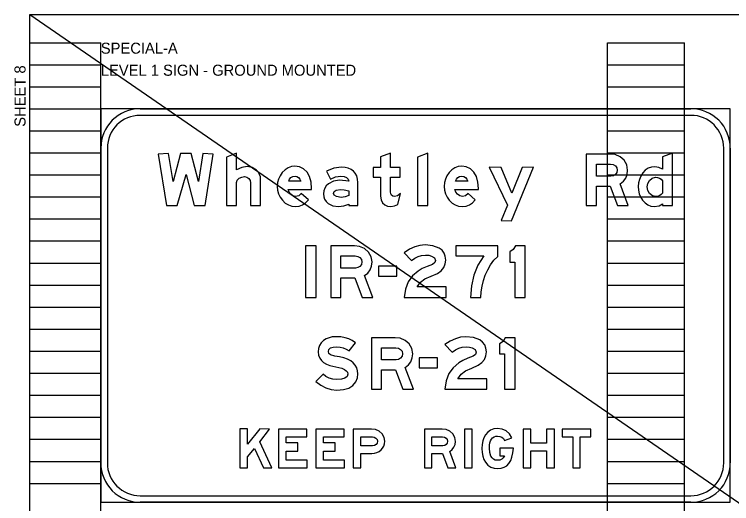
# Model space of a CAD drawing. Extents: x 1820207 to 1820557, y 740216 to 740315.
# Drawn here: x 1820476.25 to 1820485.37, y 740308.38 to 740314.6 of the extents above; entities that cross this region are included whole.
import ezdxf

# ---------------------------------------------------------------- set-up
doc = ezdxf.new("R2010")
doc.units = 0
for name, color, linetype in [('SC_Scratch1', 7, 'Continuous'), ('SC_Scratch2', 7, 'Continuous'), ('SC_Scratch3', 7, 'Continuous'), ('SC_Shading1', 7, 'Continuous'), ('SH_Text', 7, 'Continuous')]:
    doc.layers.add(name, color=color, linetype=linetype)

msp = doc.modelspace()

# ---------------------------------------------------------------- linework, layer by layer
at = {"layer": 'SC_Scratch1'}
for p, q in [((1820476.451, 740294.0812), (1820476.451, 740314.2412)), ((1820476.451, 740314.2412), (1820477.351, 740314.2412)), ((1820477.351, 740294.0812), (1820477.351, 740314.2412)), ((1820483.791, 740294.0812), (1820483.791, 740314.2412)), ((1820483.791, 740314.2412), (1820484.771, 740314.2412)), ((1820484.771, 740294.0812), (1820484.771, 740314.2412)), ((1820476.451, 740313.9612), (1820477.351, 740313.9612)), ((1820483.791, 740313.9612), (1820484.771, 740313.9612)), ((1820476.451, 740313.6812), (1820477.351, 740313.6812)), ((1820483.791, 740313.6812), (1820484.771, 740313.6812)), ((1820476.451, 740313.4012), (1820477.351, 740313.4012)), ((1820483.791, 740313.4012), (1820484.771, 740313.4012)), ((1820476.451, 740313.1212), (1820477.351, 740313.1212)), ((1820483.791, 740313.1212), (1820484.771, 740313.1212)), ((1820476.451, 740312.8412), (1820477.351, 740312.8412)), ((1820483.791, 740312.8412), (1820484.771, 740312.8412)), ((1820476.451, 740312.5612), (1820477.351, 740312.5612)), ((1820483.791, 740312.5612), (1820484.771, 740312.5612)), ((1820476.451, 740312.2812), (1820477.351, 740312.2812)), ((1820483.791, 740312.2812), (1820484.771, 740312.2812)), ((1820476.451, 740312.0012), (1820477.351, 740312.0012)), ((1820483.791, 740312.0012), (1820484.771, 740312.0012)), ((1820476.451, 740311.7212), (1820477.351, 740311.7212)), ((1820483.791, 740311.7212), (1820484.771, 740311.7212)), ((1820476.451, 740311.4412), (1820477.351, 740311.4412)), ((1820483.791, 740311.4412), (1820484.771, 740311.4412)), ((1820476.451, 740311.1612), (1820477.351, 740311.1612)), ((1820483.791, 740311.1612), (1820484.771, 740311.1612)), ((1820476.451, 740310.8812), (1820477.351, 740310.8812)), ((1820483.791, 740310.8812), (1820484.771, 740310.8812)), ((1820476.451, 740310.6012), (1820477.351, 740310.6012)), ((1820483.791, 740310.6012), (1820484.771, 740310.6012)), ((1820476.451, 740310.3212), (1820477.351, 740310.3212)), ((1820483.791, 740310.3212), (1820484.771, 740310.3212)), ((1820476.451, 740310.0412), (1820477.351, 740310.0412)), ((1820483.791, 740310.0412), (1820484.771, 740310.0412)), ((1820476.451, 740309.7612), (1820477.351, 740309.7612)), ((1820483.791, 740309.7612), (1820484.771, 740309.7612)), ((1820476.451, 740309.4812), (1820477.351, 740309.4812)), ((1820483.791, 740309.4812), (1820484.771, 740309.4812)), ((1820476.451, 740309.2012), (1820477.351, 740309.2012)), ((1820483.791, 740309.2012), (1820484.771, 740309.2012)), ((1820476.451, 740308.9212), (1820477.351, 740308.9212)), ((1820483.791, 740308.9212), (1820484.771, 740308.9212)), ((1820476.451, 740308.6412), (1820477.351, 740308.6412)), ((1820483.791, 740308.6412), (1820484.771, 740308.6412))]:
    msp.add_line(p, q, dxfattribs=at)
at = {"layer": 'SC_Scratch2'}
msp.add_lwpolyline([(1820476.451, 740314.6012), (1820506.951, 740314.6012), (1820506.951, 740293.6012), (1820476.451, 740293.6012)], close=True, dxfattribs=at)
at = {"layer": 'SC_Scratch3'}
for points in [[(1820477.351, 740308.4012), (1820485.351, 740308.4012), (1820485.351, 740313.4012), (1820477.351, 740313.4012), (1820477.351, 740308.4012), (1820477.351, 740308.4012), (1820477.351, 740308.4012)], [(1820477.851, 740313.4012), (1820484.851, 740313.4012)], [(1820484.851, 740313.3178), (1820477.851, 740313.3178)], [(1820484.851, 740313.3178), (1820484.851, 740313.3178), (1820484.851, 740313.3178)], [(1820477.351, 740308.9012), (1820477.351, 740312.9012)], [(1820477.4343, 740312.9012), (1820477.4343, 740308.9012)], [(1820477.4343, 740312.9012), (1820477.4343, 740312.9012), (1820477.4343, 740312.9012)], [(1820485.2676, 740308.9012), (1820485.2676, 740312.9012)], [(1820485.351, 740312.9012), (1820485.351, 740308.9012)], [(1820485.2676, 740308.9012), (1820485.2676, 740308.9012), (1820485.2676, 740308.9012)], [(1820477.851, 740308.4845), (1820484.851, 740308.4845)], [(1820477.851, 740308.4845), (1820477.851, 740308.4845), (1820477.851, 740308.4845)], [(1820484.851, 740308.4012), (1820477.851, 740308.4012)]]:
    msp.add_lwpolyline(points, dxfattribs=at)
for points in [[(1820478.1845, 740312.172), (1820478.3229, 740312.172), (1820478.4363, 740312.567), (1820478.5378, 740312.172), (1820478.6763, 740312.172), (1820478.7799, 740312.8258), (1820478.6487, 740312.8312), (1820478.5933, 740312.4778), (1820478.501, 740312.8312), (1820478.3624, 740312.8312), (1820478.2702, 740312.4778), (1820478.2121, 740312.8312), (1820478.081, 740312.8258)], [(1820478.9476, 740312.172), (1820479.0758, 740312.172), (1820479.0758, 740312.4652), (1820479.0846, 740312.4945), (1820479.1113, 740312.5193), (1820479.1433, 740312.5341), (1820479.1768, 740312.5392), (1820479.2074, 740312.5333), (1820479.2326, 740312.5161), (1820479.2495, 740312.4907), (1820479.2552, 740312.4607), (1820479.2552, 740312.172), (1820479.3827, 740312.172), (1820479.3827, 740312.5049), (1820479.3793, 740312.5377), (1820479.3697, 740312.5682), (1820479.3532, 740312.5958), (1820479.3306, 740312.6211), (1820479.2749, 740312.6552), (1820479.2096, 740312.6666), (1820479.1449, 740312.6565), (1820479.0758, 740312.6269), (1820479.0758, 740312.8387), (1820478.9476, 740312.7881)], [(1820480.8143, 740312.531), (1820480.9052, 740312.531), (1820480.9046, 740312.2911), (1820480.9132, 740312.2441), (1820480.932, 740312.2059), (1820480.9591, 740312.179), (1820480.9943, 740312.1635), (1820481.0378, 740312.1592), (1820481.0833, 740312.1666), (1820481.1242, 740312.1854), (1820481.1584, 740312.325), (1820481.1238, 740312.2968), (1820481.0833, 740312.2873), (1820481.0614, 740312.291), (1820481.0461, 740312.302), (1820481.0368, 740312.3202), (1820481.0338, 740312.3458), (1820481.0338, 740312.531), (1820481.1572, 740312.531), (1820481.1572, 740312.6534), (1820481.0338, 740312.6534), (1820481.0338, 740312.8387), (1820480.9052, 740312.7888), (1820480.9052, 740312.6534), (1820480.8143, 740312.6534)], [(1820481.3743, 740312.172), (1820481.506, 740312.172), (1820481.506, 740312.8387), (1820481.3743, 740312.7881)], [(1820483.9502, 740312.4478), (1820483.9919, 740312.4811), (1820484.0217, 740312.5211), (1820484.0398, 740312.5678), (1820484.0458, 740312.6211), (1820484.0345, 740312.6874), (1820484.0013, 740312.7463), (1820483.9506, 740312.7921), (1820483.8875, 740312.8192), (1820483.8202, 740312.8258), (1820483.521, 740312.8258), (1820483.521, 740312.172), (1820483.6491, 740312.172), (1820483.6491, 740312.4179), (1820483.8262, 740312.4179), (1820483.9183, 740312.172), (1820484.055, 740312.172)], [(1820484.4886, 740312.172), (1820484.616, 740312.172), (1820484.616, 740312.8387), (1820484.4886, 740312.789), (1820484.4886, 740312.6321), (1820484.4429, 740312.6567), (1820484.3933, 740312.6652), (1820484.3486, 740312.6601), (1820484.3082, 740312.6452), (1820484.2713, 740312.6201), (1820484.2386, 740312.5853), (1820484.2133, 740312.5462), (1820484.1954, 740312.5043), (1820484.1845, 740312.4594), (1820484.181, 740312.4118), (1820484.1843, 740312.3657), (1820484.1945, 740312.3222), (1820484.2118, 740312.2807), (1820484.236, 740312.2419), (1820484.2679, 740312.2055), (1820484.3034, 740312.1798), (1820484.3422, 740312.1642), (1820484.3848, 740312.1592), (1820484.4454, 740312.168), (1820484.4886, 740312.1944)], [(1820479.9899, 740312.2461), (1820479.8995, 740312.3257), (1820479.8673, 740312.2968), (1820479.8264, 740312.2873), (1820479.7933, 740312.2942), (1820479.7645, 740312.3152), (1820479.7433, 740312.3435), (1820479.7315, 740312.3771), (1820480.0294, 740312.3771), (1820480.0294, 740312.3882), (1820480.0236, 740312.4707), (1820480.0049, 740312.5395), (1820479.9729, 740312.5949), (1820479.9278, 740312.6369), (1820479.8749, 740312.6631), (1820479.819, 740312.672), (1820479.7729, 740312.6668), (1820479.7307, 740312.6515), (1820479.6922, 740312.6261), (1820479.6575, 740312.5909), (1820479.6297, 740312.5508), (1820479.6101, 740312.5083), (1820479.598, 740312.463), (1820479.5943, 740312.4152), (1820479.5983, 740312.3659), (1820479.6105, 740312.3202), (1820479.6309, 740312.2776), (1820479.6596, 740312.2383), (1820479.6952, 740312.2034), (1820479.7351, 740312.1788), (1820479.7788, 740312.164), (1820479.8264, 740312.1592), (1820479.8723, 740312.1646), (1820479.9149, 740312.1808), (1820479.954, 740312.2078)], [(1820480.5014, 740312.172), (1820480.6166, 740312.172), (1820480.6166, 740312.463), (1820480.613, 740312.5081), (1820480.6028, 740312.5477), (1820480.5853, 740312.5816), (1820480.5613, 740312.6101), (1820480.5317, 740312.6313), (1820480.4966, 740312.6467), (1820480.4558, 740312.656), (1820480.4097, 740312.6591), (1820480.3138, 740312.6467), (1820480.2203, 740312.6097), (1820480.2697, 740312.5089), (1820480.3352, 740312.535), (1820480.4003, 740312.5438), (1820480.4432, 740312.5398), (1820480.4744, 740312.5281), (1820480.4936, 740312.5085), (1820480.5014, 740312.4813), (1820480.3864, 740312.4925), (1820480.3089, 740312.4815), (1820480.2448, 740312.4484), (1820480.2168, 740312.4223), (1820480.1967, 740312.3923), (1820480.1847, 740312.3583), (1820480.181, 740312.3202), (1820480.1845, 740312.2833), (1820480.1955, 740312.2509), (1820480.2138, 740312.2226), (1820480.2394, 740312.1986), (1820480.2995, 740312.1691), (1820480.3738, 740312.1592), (1820480.4399, 740312.1665), (1820480.5014, 740312.1884)], [(1820482.1099, 740312.2461), (1820482.0195, 740312.3257), (1820481.9873, 740312.2968), (1820481.9464, 740312.2873), (1820481.9133, 740312.2942), (1820481.8845, 740312.3152), (1820481.8633, 740312.3435), (1820481.8515, 740312.3771), (1820482.1494, 740312.3771), (1820482.1494, 740312.3882), (1820482.1436, 740312.4707), (1820482.1249, 740312.5395), (1820482.0929, 740312.5949), (1820482.0478, 740312.6369), (1820481.9949, 740312.6631), (1820481.939, 740312.672), (1820481.8929, 740312.6668), (1820481.8507, 740312.6515), (1820481.8122, 740312.6261), (1820481.7775, 740312.5909), (1820481.7497, 740312.5508), (1820481.7301, 740312.5083), (1820481.718, 740312.463), (1820481.7143, 740312.4152), (1820481.7183, 740312.3659), (1820481.7305, 740312.3202), (1820481.7509, 740312.2776), (1820481.7796, 740312.2383), (1820481.8152, 740312.2034), (1820481.8551, 740312.1788), (1820481.8988, 740312.164), (1820481.9464, 740312.1592), (1820481.9923, 740312.1646), (1820482.0349, 740312.1808), (1820482.074, 740312.2078)], [(1820482.2876, 740312.6591), (1820482.5178, 740312.1752), (1820482.4379, 740311.9797), (1820482.5711, 740311.9775), (1820482.8481, 740312.6591), (1820482.7071, 740312.6534), (1820482.5738, 740312.3288), (1820482.4398, 740312.6534)], [(1820483.9152, 740312.6217), (1820483.9091, 740312.5902), (1820483.8915, 740312.5654), (1820483.865, 740312.5492), (1820483.8335, 740312.5438), (1820483.6491, 740312.5438), (1820483.6491, 740312.6976), (1820483.8306, 740312.6976), (1820483.8631, 740312.6924), (1820483.8905, 740312.677), (1820483.909, 740312.6527)], [(1820479.8949, 740312.4796), (1820479.7387, 740312.4796), (1820479.7507, 740312.5077), (1820479.7681, 740312.5277), (1820479.791, 740312.5398), (1820479.8192, 740312.5438), (1820479.8435, 740312.5398), (1820479.8641, 740312.5277), (1820479.8811, 740312.5077)], [(1820482.0149, 740312.4796), (1820481.8587, 740312.4796), (1820481.8707, 740312.5077), (1820481.8881, 740312.5277), (1820481.911, 740312.5398), (1820481.9392, 740312.5438), (1820481.9635, 740312.5398), (1820481.9841, 740312.5277), (1820482.0011, 740312.5077)], [(1820484.4886, 740312.3302), (1820484.474, 740312.3114), (1820484.4555, 740312.298), (1820484.4327, 740312.2899), (1820484.4063, 740312.2873), (1820484.3606, 740312.2966), (1820484.3248, 740312.3244), (1820484.3034, 740312.3623), (1820484.2963, 740312.4075), (1820484.3027, 740312.4516), (1820484.3226, 740312.4907), (1820484.3562, 740312.5207), (1820484.3995, 740312.531), (1820484.4275, 740312.528), (1820484.452, 740312.5195), (1820484.4722, 740312.5051), (1820484.4886, 740312.4855)], [(1820480.5014, 740312.2988), (1820480.4568, 740312.2806), (1820480.4047, 740312.2745), (1820480.3448, 740312.2858), (1820480.3179, 740312.3034), (1820480.3091, 740312.3268), (1820480.3169, 740312.3505), (1820480.3404, 740312.3671), (1820480.3956, 740312.3771), (1820480.4459, 740312.3723), (1820480.5014, 740312.3579)], [(1820479.9543, 740311.0053), (1820480.086, 740311.0053), (1820480.086, 740311.6591), (1820479.9543, 740311.6591)], [(1820480.7036, 740311.2811), (1820480.7452, 740311.3144), (1820480.775, 740311.3545), (1820480.7931, 740311.4012), (1820480.7991, 740311.4544), (1820480.7879, 740311.5207), (1820480.7546, 740311.5796), (1820480.704, 740311.6255), (1820480.6408, 740311.6526), (1820480.5735, 740311.6591), (1820480.2743, 740311.6591), (1820480.2743, 740311.0053), (1820480.4025, 740311.0053), (1820480.4025, 740311.2513), (1820480.5795, 740311.2513), (1820480.6717, 740311.0053), (1820480.8083, 740311.0053)], [(1820481.2076, 740311.0053), (1820481.7416, 740311.0053), (1820481.7416, 740311.1371), (1820481.3719, 740311.1371), (1820481.4145, 740311.1968), (1820481.4694, 740311.2397), (1820481.5506, 740311.2737), (1820481.6302, 740311.3092), (1820481.676, 740311.344), (1820481.7088, 740311.3841), (1820481.7285, 740311.429), (1820481.7351, 740311.4789), (1820481.7296, 740311.5265), (1820481.7138, 740311.5678), (1820481.6874, 740311.6027), (1820481.6507, 740311.6313), (1820481.5718, 740311.6618), (1820481.4726, 740311.672), (1820481.4073, 740311.6656), (1820481.3414, 740311.6467), (1820481.2747, 740311.6153), (1820481.2076, 740311.5714), (1820481.3006, 740311.4755), (1820481.341, 740311.5049), (1820481.3839, 740311.5259), (1820481.4287, 740311.5385), (1820481.476, 740311.5428), (1820481.5183, 740311.5395), (1820481.5558, 740311.5302), (1820481.5928, 740311.5075), (1820481.6052, 740311.4755), (1820481.595, 740311.4476), (1820481.565, 740311.4234), (1820481.499, 740311.3978), (1820481.437, 740311.3711), (1820481.3831, 740311.3397), (1820481.312, 740311.2781), (1820481.2593, 740311.2022), (1820481.2242, 740311.1111)], [(1820481.861, 740311.5347), (1820482.2183, 740311.5347), (1820482.1446, 740311.4142), (1820482.0921, 740311.2859), (1820482.0607, 740311.1495), (1820482.0502, 740311.0053), (1820482.182, 740311.0053), (1820482.1854, 740311.0762), (1820482.1958, 740311.1469), (1820482.2131, 740311.2173), (1820482.2375, 740311.2872), (1820482.2688, 740311.3567), (1820482.3055, 740311.4196), (1820482.3475, 740311.4759), (1820482.395, 740311.5258), (1820482.395, 740311.6591), (1820481.861, 740311.6591)], [(1820482.6115, 740311.0053), (1820482.7453, 740311.0053), (1820482.7453, 740311.6591), (1820482.6207, 740311.6591), (1820482.593, 740311.6128), (1820482.5476, 740311.5827), (1820482.5476, 740311.4536), (1820482.6115, 740311.4536)], [(1820480.6685, 740311.455), (1820480.6625, 740311.4236), (1820480.6448, 740311.3987), (1820480.6184, 740311.3825), (1820480.5868, 740311.3771), (1820480.4025, 740311.3771), (1820480.4025, 740311.531), (1820480.5839, 740311.531), (1820480.6164, 740311.5258), (1820480.6438, 740311.5103), (1820480.6623, 740311.4861)], [(1820481.1117, 740311.4027), (1820480.881, 740311.4027), (1820480.881, 740311.2745), (1820481.1117, 740311.2745)], [(1820480.0843, 740309.9372), (1820480.1461, 740309.8883), (1820480.2117, 740309.8536), (1820480.2803, 740309.8327), (1820480.3527, 740309.8259), (1820480.4346, 740309.8325), (1820480.5019, 740309.8524), (1820480.5546, 740309.8859), (1820480.5927, 740309.933), (1820480.6119, 740309.9804), (1820480.6183, 740310.0317), (1820480.6145, 740310.073), (1820480.6037, 740310.1102), (1820480.5853, 740310.1434), (1820480.5598, 740310.1726), (1820480.527, 740310.1974), (1820480.4869, 740310.2182), (1820480.4394, 740310.2348), (1820480.3849, 740310.2475), (1820480.327, 740310.2561), (1820480.2715, 740310.2728), (1820480.2507, 740310.2906), (1820480.2439, 740310.317), (1820480.2506, 740310.3432), (1820480.271, 740310.3621), (1820480.305, 740310.3735), (1820480.3527, 740310.3773), (1820480.3935, 740310.3739), (1820480.4332, 740310.3639), (1820480.4711, 740310.3471), (1820480.5076, 740310.3238), (1820480.588, 740310.4262), (1820480.5466, 740310.4555), (1820480.5049, 740310.477), (1820480.456, 740310.4926), (1820480.4, 740310.5021), (1820480.3369, 740310.5053), (1820480.2932, 740310.5021), (1820480.2529, 740310.4926), (1820480.216, 740310.4769), (1820480.1824, 740310.4548), (1820480.1523, 740310.4253), (1820480.1309, 740310.3919), (1820480.1181, 740310.3543), (1820480.1139, 740310.3126), (1820480.1189, 740310.2719), (1820480.1343, 740310.2321), (1820480.1546, 740310.2018), (1820480.1824, 740310.1762), (1820480.2178, 740310.1552), (1820480.261, 740310.1389), (1820480.4146, 740310.1035), (1820480.447, 740310.0902), (1820480.4704, 740310.0732), (1820480.4843, 740310.0524), (1820480.4891, 740310.0276), (1820480.4803, 740309.9981), (1820480.4541, 740309.9773), (1820480.4104, 740309.9647), (1820480.3493, 740309.9607), (1820480.2994, 740309.9648), (1820480.2541, 740309.9781), (1820480.213, 740309.9997), (1820480.1766, 740310.0306)], [(1820481.2202, 740310.1145), (1820481.2619, 740310.1478), (1820481.2917, 740310.1878), (1820481.3098, 740310.2345), (1820481.3158, 740310.2877), (1820481.3045, 740310.3541), (1820481.2713, 740310.413), (1820481.2206, 740310.4588), (1820481.1575, 740310.4859), (1820481.0902, 740310.4925), (1820480.791, 740310.4925), (1820480.791, 740309.8387), (1820480.9191, 740309.8387), (1820480.9191, 740310.0846), (1820481.0962, 740310.0846), (1820481.1883, 740309.8387), (1820481.325, 740309.8387)], [(1820481.7243, 740309.8387), (1820482.2583, 740309.8387), (1820482.2583, 740309.9704), (1820481.8885, 740309.9704), (1820481.9312, 740310.0302), (1820481.9861, 740310.073), (1820482.0672, 740310.1071), (1820482.1469, 740310.1425), (1820482.1926, 740310.1774), (1820482.2254, 740310.2174), (1820482.2451, 740310.2623), (1820482.2517, 740310.3122), (1820482.2463, 740310.3598), (1820482.2305, 740310.4012), (1820482.204, 740310.436), (1820482.1673, 740310.4647), (1820482.0885, 740310.4951), (1820481.9893, 740310.5053), (1820481.924, 740310.4989), (1820481.8581, 740310.48), (1820481.7913, 740310.4486), (1820481.7243, 740310.4048), (1820481.8172, 740310.3088), (1820481.8577, 740310.3383), (1820481.9006, 740310.3593), (1820481.9454, 740310.3719), (1820481.9927, 740310.3761), (1820482.0349, 740310.3729), (1820482.0724, 740310.3635), (1820482.1095, 740310.3409), (1820482.1219, 740310.3088), (1820482.1117, 740310.281), (1820482.0816, 740310.2567), (1820482.0157, 740310.2311), (1820481.9536, 740310.2044), (1820481.8997, 740310.173), (1820481.8286, 740310.1115), (1820481.776, 740310.0355), (1820481.7409, 740309.9444)], [(1820482.4815, 740309.8387), (1820482.6153, 740309.8387), (1820482.6153, 740310.4925), (1820482.4907, 740310.4925), (1820482.463, 740310.4462), (1820482.4176, 740310.416), (1820482.4176, 740310.2869), (1820482.4815, 740310.2869)], [(1820481.1852, 740310.2884), (1820481.1791, 740310.2569), (1820481.1615, 740310.2321), (1820481.135, 740310.2159), (1820481.1035, 740310.2104), (1820480.9191, 740310.2104), (1820480.9191, 740310.3643), (1820481.1006, 740310.3643), (1820481.1331, 740310.3591), (1820481.1605, 740310.3436), (1820481.179, 740310.3194)], [(1820481.6283, 740310.2361), (1820481.3976, 740310.2361), (1820481.3976, 740310.1079), (1820481.6283, 740310.1079)], [(1820479.1185, 740308.8387), (1820479.2153, 740308.8387), (1820479.2153, 740308.9787), (1820479.3028, 740309.0845), (1820479.4171, 740308.8387), (1820479.5264, 740308.8387), (1820479.3701, 740309.1677), (1820479.4952, 740309.329), (1820479.3721, 740309.3331), (1820479.2153, 740309.1377), (1820479.2153, 740309.3331), (1820479.1185, 740309.3331)], [(1820479.9744, 740308.9348), (1820479.7049, 740308.9348), (1820479.7049, 740309.0502), (1820479.8538, 740309.0502), (1820479.8538, 740309.1559), (1820479.7049, 740309.1559), (1820479.7049, 740309.2329), (1820479.9675, 740309.2329), (1820479.9675, 740309.329), (1820479.6085, 740309.329), (1820479.6085, 740308.8387), (1820479.9744, 740308.8387)], [(1820480.4494, 740308.9348), (1820480.1799, 740308.9348), (1820480.1799, 740309.0502), (1820480.3288, 740309.0502), (1820480.3288, 740309.1559), (1820480.1799, 740309.1559), (1820480.1799, 740309.2329), (1820480.4425, 740309.2329), (1820480.4425, 740309.329), (1820480.0835, 740309.329), (1820480.0835, 740308.8387), (1820480.4494, 740308.8387)], [(1820480.5585, 740308.8387), (1820480.6546, 740308.8387), (1820480.6546, 740309.0231), (1820480.7964, 740309.0231), (1820480.8298, 740309.0257), (1820480.8603, 740309.0337), (1820480.8879, 740309.0469), (1820480.9125, 740309.0655), (1820480.9327, 740309.0882), (1820480.9473, 740309.1143), (1820480.956, 740309.1436), (1820480.959, 740309.1764), (1820480.9507, 740309.2255), (1820480.9264, 740309.2695), (1820480.8893, 740309.3039), (1820480.8433, 740309.3242), (1820480.7933, 740309.329), (1820480.5585, 740309.329)], [(1820481.7854, 740309.0455), (1820481.8167, 740309.0705), (1820481.839, 740309.1005), (1820481.8526, 740309.1355), (1820481.8571, 740309.1755), (1820481.8487, 740309.2252), (1820481.8237, 740309.2694), (1820481.7857, 740309.3038), (1820481.7384, 740309.3241), (1820481.6879, 740309.329), (1820481.4635, 740309.329), (1820481.4635, 740308.8387), (1820481.5596, 740308.8387), (1820481.5596, 740309.0231), (1820481.6924, 740309.0231), (1820481.7615, 740308.8387), (1820481.864, 740308.8387)], [(1820481.9735, 740308.8387), (1820482.0723, 740308.8387), (1820482.0723, 740309.329), (1820481.9735, 740309.329)], [(1820482.4242, 740309.0887), (1820482.4242, 740308.9925), (1820482.4831, 740308.9925), (1820482.4666, 740308.9673), (1820482.4458, 740308.9492), (1820482.4209, 740308.9384), (1820482.3919, 740308.9348), (1820482.365, 740308.9381), (1820482.3423, 740308.9482), (1820482.3235, 740308.965), (1820482.3087, 740308.9886), (1820482.2942, 740309.0335), (1820482.2896, 740309.0906), (1820482.2911, 740309.126), (1820482.2961, 740309.1568), (1820482.304, 740309.183), (1820482.3156, 740309.2045), (1820482.3302, 740309.221), (1820482.3482, 740309.2329), (1820482.3694, 740309.2401), (1820482.3938, 740309.2425), (1820482.4242, 740309.2389), (1820482.4491, 740309.2281), (1820482.4684, 740309.21), (1820482.482, 740309.1848), (1820482.5752, 740309.2189), (1820482.5453, 740309.2712), (1820482.5046, 740309.3086), (1820482.4529, 740309.3311), (1820482.3902, 740309.3387), (1820482.3443, 740309.3335), (1820482.3039, 740309.3183), (1820482.2688, 740309.293), (1820482.2394, 740309.2577), (1820482.2191, 740309.2207), (1820482.2049, 740309.1799), (1820482.1963, 740309.1348), (1820482.1935, 740309.0858), (1820482.1963, 740309.0347), (1820482.2052, 740308.9883), (1820482.2197, 740308.9465), (1820482.2405, 740308.9095), (1820482.2705, 740308.8743), (1820482.3066, 740308.8492), (1820482.3483, 740308.834), (1820482.3961, 740308.8291), (1820482.4396, 740308.8331), (1820482.4777, 740308.8453), (1820482.5104, 740308.8655), (1820482.5381, 740308.8939), (1820482.56, 740308.9305), (1820482.5768, 740308.9751), (1820482.5882, 740309.0278), (1820482.5944, 740309.0887)], [(1820482.7185, 740308.8387), (1820482.8146, 740308.8387), (1820482.8146, 740309.0557), (1820483.0165, 740309.0557), (1820483.0165, 740308.8387), (1820483.1179, 740308.8387), (1820483.1179, 740309.329), (1820483.0165, 740309.329), (1820483.0165, 740309.1542), (1820482.8146, 740309.1542), (1820482.8146, 740309.329), (1820482.7185, 740309.329)], [(1820483.3494, 740308.8387), (1820483.4444, 740308.8387), (1820483.4444, 740309.2347), (1820483.5794, 740309.2347), (1820483.5794, 740309.329), (1820483.2135, 740309.329), (1820483.2135, 740309.2347), (1820483.3494, 740309.2347)], [(1820480.6546, 740309.1175), (1820480.6546, 740309.2329), (1820480.8028, 740309.2329), (1820480.8269, 740309.229), (1820480.8473, 740309.2174), (1820480.8613, 740309.1992), (1820480.8661, 740309.176), (1820480.8617, 740309.1523), (1820480.8489, 740309.1337), (1820480.8295, 740309.1216), (1820480.8059, 740309.1175)], [(1820481.7591, 740309.176), (1820481.7546, 740309.1523), (1820481.7414, 740309.1337), (1820481.7215, 740309.1216), (1820481.6978, 740309.1175), (1820481.5596, 740309.1175), (1820481.5596, 740309.2329), (1820481.6957, 740309.2329), (1820481.7201, 740309.229), (1820481.7406, 740309.2174), (1820481.7545, 740309.1992)]]:
    msp.add_lwpolyline(points, close=True, dxfattribs=at)
for centre, radius, start, end in [((1820477.851, 740312.9012), 0.5, 90.00021, 179.99985), ((1820484.851, 740312.9012), 0.5, 0, 90.00021), ((1820477.851, 740312.9012), 0.4167, 90.00021, 179.99985), ((1820484.851, 740312.9012), 0.4167, 0, 90.00021), ((1820477.851, 740308.9012), 0.5, 179.99985, 270.00006), ((1820477.851, 740308.9012), 0.4167, 179.99985, 270.00006), ((1820484.851, 740308.9012), 0.5, 270.00006, 0.00027), ((1820484.851, 740308.9012), 0.4167, 270.00006, 0.00027)]:
    msp.add_arc(centre, radius, start, end, dxfattribs=at)
at = {"layer": 'SC_Shading1'}
msp.add_lwpolyline([(1820476.451, 740314.6012), (1820506.951, 740293.6012)], dxfattribs=at)

# ---------------------------------------------------------------- texts
at = {"layer": 'SH_Text'}
for s, p in [('SPECIAL-A', (1820477.351, 740314.1012)), ('LEVEL 1 SIGN - GROUND MOUNTED', (1820477.351, 740313.8212))]:
    msp.add_text(s, height=0.14, dxfattribs=at).set_placement(p)
msp.add_text('SHEET 8', height=0.14, rotation=90, dxfattribs=at).set_placement((1820476.3944, 740313.1724))

doc.saveas('drawing.dxf')
